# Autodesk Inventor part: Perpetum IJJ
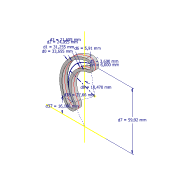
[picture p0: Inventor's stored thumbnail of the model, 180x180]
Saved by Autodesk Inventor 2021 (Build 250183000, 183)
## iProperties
Created: 2023-12
Part Number: Perpetum IJJ
Material: Všeobecné
Document SubType Name: Modeling
Designer: tatulinek
Density: 1 g/cm^3
Appearance: Výchozí
Author: tatulinek
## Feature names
1. Vysunutí1 [Extrusion]
2. Vybrání - Pro kuličku
## Parameters: d0 = 33.655 mm, d1 = 31.255 mm, d2 = 24.055 mm, d3 = 21.655 mm, d4 = 6 mm, d5 = 3.6 mm, d6 = 5.91 mm, d7 = 59.92 mm, d8 = 10.47037 mm, d14 = 6 mm, d15 = 0, d19 = 6.28105 mm, d20 = 21.98901 mm, d22 = 1.51 mm, d23 = 6.2 mm, d24 = 1.51 mm, d25 = 0, d26 = 0, d37 = 16.18596 mm, d38 = 27.66 mm
